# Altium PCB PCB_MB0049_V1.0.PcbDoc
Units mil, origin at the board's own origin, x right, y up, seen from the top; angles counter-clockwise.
Board outline 787.4 x 3937.01 mil, 2 copper layers (Top Layer, Bottom Layer); 21 components, 22 nets, 58 pads, 9 vias.
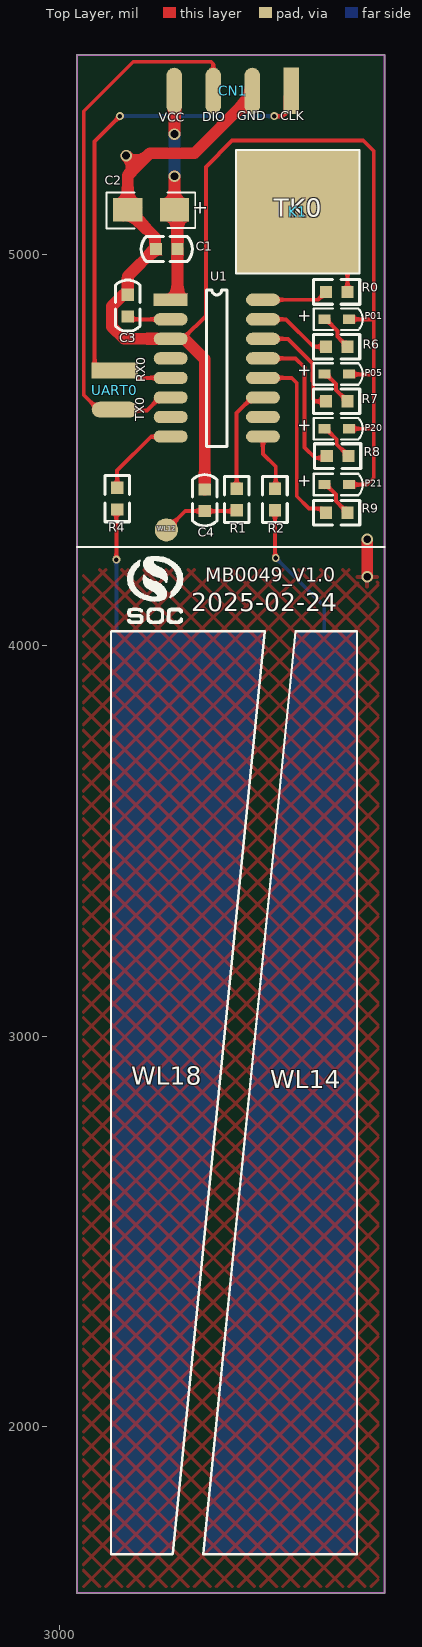
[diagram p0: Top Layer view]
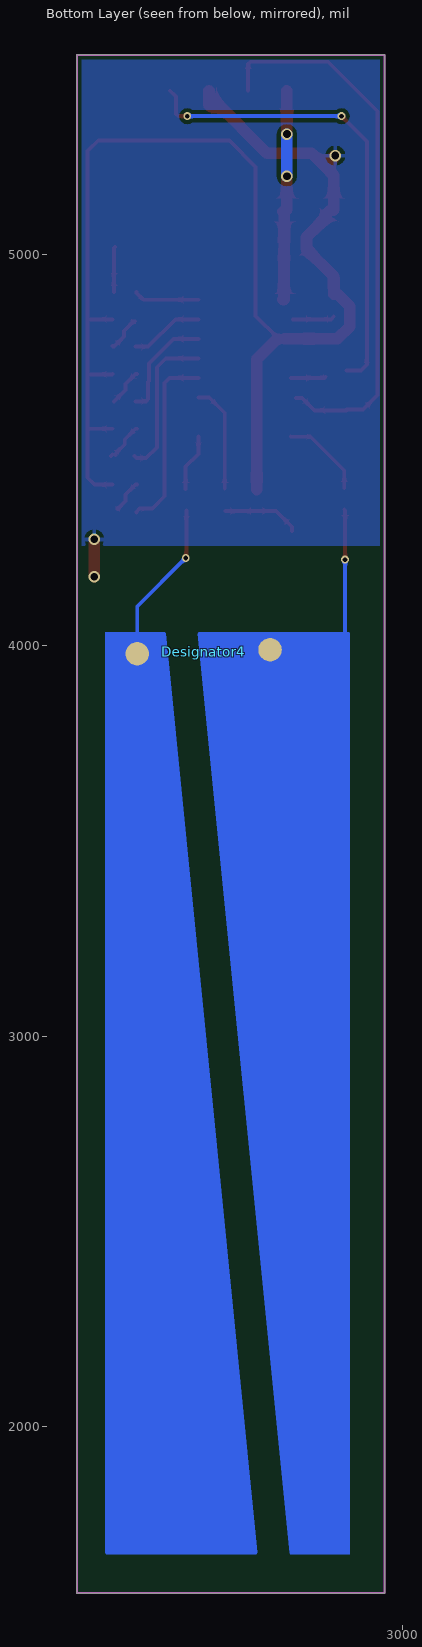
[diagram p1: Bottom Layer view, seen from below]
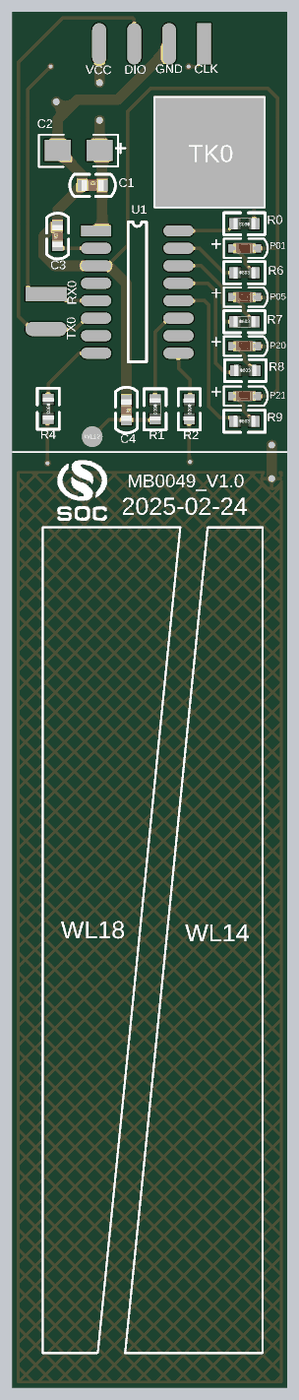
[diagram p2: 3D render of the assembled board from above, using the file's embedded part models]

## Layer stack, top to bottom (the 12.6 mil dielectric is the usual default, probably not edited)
Top Solder: solder mask 0.4, Solder Resist, Dk 3.5
Top Layer: signal copper 1.4
Dielectric 1: dielectric 12.6, FR-4, Dk 4.8
Bottom Layer: signal copper 1.4
Bottom Solder: solder mask 0.4, Solder Resist, Dk 3.5

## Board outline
3045,1574.8 3045,5511.81 3832.4,5511.81 3832.4,1574.8

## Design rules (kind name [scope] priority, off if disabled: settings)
Clearance [All] p1: gap=10 ignorepadtopadclearanceinfootprint=FALSE except(0: Arc-Hole Track-Hole SMDPad-Hole THPad-Hole Via-Hole Fill-Hole Poly-Hole Region-Hole Text-Hole)
PolygonConnect [All] p1: connectstyle=Relief reliefconductorwidth=10 reliefentries=4 polygonreliefangle="90 Angle" airgapwidth=10
RoutingVias [All] p1: holewidth=28 width=50 viastyle="Through Hole" minholewidth=28 minwidth=50 maxholewidth=28 maxwidth=50
SolderMaskExpansion [All] p1: expansion=4 istentingtop=FALSE
Width [All] p1: maxlimit=30 minlimit=10 preferedwidth=10
30 further rules are at their usual default settings.

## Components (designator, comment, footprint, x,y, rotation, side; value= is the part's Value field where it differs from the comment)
C1 "104" C0603-SMT 3275,5015 r0 top
C2 "A/10uF/16V" A-3216 3295,5115 r180 top
C3 "103" C0603-SMT 3175,4870 r90 top
C4 "15pf" C0603-SMT 3372,4372 r270 top
CN1 "CN4" HDR2.54-WS-4P 3444,5361.26 r180 top
Designator4 "Comment" KEY-WL38-1 3438,3264 r0 top
K1 "K-QM" KEY-WL38-2 3610,5110 r0 top
P01 "LED" LED-0603-SMT 3710,4835 r0 top (schematic designator L1)
P05 "LED" LED-0603-SMT 3710,4695 r0 top (schematic designator L2)
P20 "LED" LED-0603-SMT 3710,4555 r0 top (schematic designator L3)
P21 "LED" LED-0603-SMT 3710,4412 r0 top (schematic designator L4)
R0 "510R" R0603-SMT 3710,4905 r180 top
R1 "510R" R0603-SMT 3454,4374 r270 top
R2 "510R" R0603-SMT 3552,4374 r270 top
R4 "510R" R0603-SMT 3148,4376 r270 top
R6 "5.1K" R0603-SMT 3710,4765 r0 top
R7 "5.1K" R0603-SMT 3710,4625 r0 top
R8 "5.1K" R0603-SMT 3712.44,4485 r0 top
R9 "5.1K" R0603-SMT 3710,4340 r0 top
U1 "SC92F8481" SOP16 3285,4885 r0 top
UART0 "CON1*2" HDR2.54-WS-2P 3205.74,4654 r270 top

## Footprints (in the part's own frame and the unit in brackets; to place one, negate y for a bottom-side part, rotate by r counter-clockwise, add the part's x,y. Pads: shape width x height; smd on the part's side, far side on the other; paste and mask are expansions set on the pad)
A-3216 [mil]
  rect 75x60 smd: 1(0,0) 2(120,0)
  silkscreen extent -53,-45 174,47
C0603-SMT [mm]
  rect 0.8x0.8 smd: 1(-0.7,0) 2(0.7,0)
  silkscreen extent -1.66,-0.8 1.66,0.8, body extent -0.8,-0.4 0.8,0.4, height 0.3
HDR2.54-WS-2P [mm] "2P卧式贴片排针2.54"
  rect 1.02x3 smd: 1(-1.27,-1.619)
  oval 1.02x3 smd: 2(1.27,-1.619)
HDR2.54-WS-4P [mm] "4P卧式贴片排针2.54"
  rect 1.02x3 smd: 1(-3.81,-1.492)
  oval 1.02x3 smd: 2(-1.27,-1.492) 3(1.27,-1.492) 4(3.81,-1.492)
KEY-WL38-1 [mil]
  round 60 smd far side: 1(-100,725) 2(240,715)
  Bottom Layer region: 319.77,-1589.7 -64.5,-1589.7 -67.86,-1586 167.45,767.09 319.77,767.09
  Bottom Layer region: 83.34,763.59 -151.97,-1589.5 -304.29,-1589.5 -304.29,767.29 79.98,767.29
  Bottom Layer region: 320.77,-1587.7 -63.5,-1587.7 -66.86,-1584 168.45,769.09 320.77,769.09
  Bottom Layer region: 84.34,765.59 -150.97,-1587.5 -303.29,-1587.5 -303.29,769.29 80.98,769.29
  Bottom Layer region: 321.77,-1586.7 -62.5,-1586.7 -65.86,-1583 169.45,770.09 321.77,770.09
  Bottom Layer region: 85.34,766.59 -149.97,-1586.5 -302.29,-1586.5 -302.29,770.29 81.98,770.29
  silkscreen extent -306,-1590 324,773
KEY-WL38-2 [mm]
  rect 8x8 smd mask+0.102: 1(0,0)
LED-0603-SMT [mm]
  rect 0.8x0.6 smd: A(-0.8,0) K(0.8,0)
  silkscreen extent -1.5,-0.7 1.69,0.7, body extent -0.81,-0.4 0.81,0.4, height 0.6
R0603-SMT [mm]
  rect 0.8x0.8 smd: 1(-0.7,0) 2(0.7,0)
  silkscreen extent -1.5,-0.8 1.5,0.8, body extent -0.8,-0.41 0.8,0.41, height 0.45
SOP16 [mm]
  rect 2.2x0.8 smd: 1(0,0)
  oval 2.2x0.8 smd: 2(0,-1.27) 3(0,-2.54) 4(0,-3.81) 5(0,-5.08) 6(0,-6.35) 7(0,-7.62) 8(0,-8.89) 9(6,-8.89) 10(6,-7.62) 11(6,-6.35) 12(6,-5.08) 13(6,-3.81) 14(6,-2.54) 15(6,-1.27) 16(6,0)
  silkscreen extent 2.33,-9.53 3.67,0.64

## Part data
C1 C4: library part C_3, "C"
C2: library part T-A/10uF/16V
C3: library part C_1, "C"
CN1: "4P-SOCKET"
R0 R1 R2 R4 R6 R7 R8 R9: library part R, "RES"
U1: "电压:2.4V-5.5V;ROM:128KB;RAM:256B+8KB;32/16/8/4MHz"

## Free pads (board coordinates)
  round 59.06 smd mask+4: 2(3274,4296)

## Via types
v1: diameter 30, hole 20, Top Layer to Bottom Layer, tented both sides, 5 vias
v2: diameter 20, hole 12, Top Layer to Bottom Layer, tented both sides, 4 vias

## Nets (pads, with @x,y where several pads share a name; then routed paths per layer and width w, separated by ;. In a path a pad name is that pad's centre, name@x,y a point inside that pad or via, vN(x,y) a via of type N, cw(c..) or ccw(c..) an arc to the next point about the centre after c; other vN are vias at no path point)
CLK: CN1.1 U1.5 UART0.1 | length 1302.9
  Top Layer w10: UART0.1 3105.44,4704 3090.37,4719.08 3090.37,4732.71 3090,4733.08 3090,5290 v2(3155,5355) ; UART0.1@3196,4688 3199,4685 U1.5 ; v2(3550,5355) 3573.06,5355 3578.92,5360.86 3578.92,5404.92 CN1.1
  Bottom Layer w10: v2(3155,5355) v2(3550,5355)
DIO: CN1.3 U1.6 UART0.2 | length 1419.2
  Top Layer w10: UART0.2@3142,4602 3224.44,4602 3256.44,4634 U1.6@3272,4634 ; UART0.2 3100,4604 3062.5,4641.5 3062.5,5367.5 3189.31,5494.31 3388.14,5494.31 3394,5488.45 CN1.3
GND: C1.1 C2.2 C3.2 C4.1 CN1.2 P01.K P05.K P20.K P21.K U1.3 | length 3661.8
  Top Layer w10: U1.3@3302,4788 3319,4788 3375,4844 3375,5225.32 3442.16,5292.48 3777.84,5292.48 3804.9,5265.41 3804.9,4429.57 3787.33,4412 P21.K ; P20.K 3799,4555 3804,4550 ; P05.K 3741.5,4694.75 3742.24,4694 3800,4694 ; P01.K 3801,4835 3802,4836
  Top Layer w30: v1(3171,5254) 3198.5,5226.5 ; C1.1@3245,5015 3175,4945 3175,4899 3164.71,4899 3134.25,4868.54 3134.25,4816.34 3165.59,4785 U1.3 U1.3@3302,4785 ; C1.1@3245,5020 3245,5045 3197.5,5092.5 3197.5,5100 3182.5,5115 C2.2 3175,5203 3198.5,5226.5 ; U1.3@3316,4784 3321.19,4784 3372,4733.19 C4.1 ; CN1.2@3486,5394 3480,5394 3346,5260 3232,5260 3198.5,5226.5 ; CN1.2@3489.31,5379.08 3494,5383.77 CN1.2 ; v1(3788,4176) v1@3788,4270
  other v1: 3788,4272
NetC3_1: C3.1 U1.2 | length 108.1
  Top Layer w10: C3.1 3182.44,4835 U1.2@3280,4835
NetC4_2: C4.2 pad.2 R1.2 | length 198.5
  Top Layer w10: pad.2@3282,4292.48 3282,4304 3322.44,4344.44 C4.2 3372.44,4344 R1.2@3452,4344
NetK0_9: 
NetK1_1: K1.1 R0.1 | length 116.1
  Top Layer w10: K1.1@3735,5020 3737.56,5017.44 R0.1
NetK2_1: Designator4.2 R2.2 | length 419.6
  Top Layer w10: R2.2 3552,4232.71 3552.09,4232.62 3552.09,4225.91 v2(3554,4224)
  Bottom Layer w10: v2(3554,4224) 3678,4100 Designator4.2
NetK4_1: Designator4.1 R4.2 | length 547
  Top Layer w10: v2(3146,4220) 3146,4346.44 R4.2
  Bottom Layer w10: v2(3146,4220) 3146,3998 3155,3989 Designator4.1
NetL1_A: P01.A R6.2 | length 91.3
  Top Layer w10: P01.A@3684,4830 3687.44,4830 3712,4805.44 3712,4790.56 R6.2 ; R6.2@3740,4765 R6.2@3741.5,4766.5
NetL2_A: P05.A R7.2 | length 96.8
  Top Layer w10: P05.A 3682.44,4695 3708,4669.44 3708,4654.56 R7.2
NetL3_A: P20.A R8.2 | length 97.2
  Top Layer w10: P20.A 3682.44,4555 3710,4527.44 3710,4515 3734,4491 R8.2@3734,4488 ; R8.2@3741.5,4488.5 R8.2@3745,4485
NetL4_A: P21.A R9.2 | length 85.1
  Top Layer w10: P21.A 3682.44,4412 3708,4386.44 3708,4369.56 3727.56,4350 R9.2@3728,4350
NetR0_2: R0.2 U1.16 | length 168.5
  Top Layer w10: U1.16 3662.44,4885 3680,4902.56 R0.2@3680,4905
NetR1_1: R1.1 U1.11 | length 277.4
  Top Layer w10: R1.1 3454,4595.34 3493.66,4635 U1.11
NetR2_1: R2.1 U1.9 | length 148.6
  Top Layer w10: U1.9 3521.22,4490.78 3554,4458 R2.1@3554,4400.02
NetR4_1: R4.1 U1.8 | length 217.5
  Top Layer w10: R4.1 3148,4448 3234.48,4534.48 3284.48,4534.48 U1.8
NetR6_1: R6.1 U1.15 | length 190.2
  Top Layer w10: U1.15 3580,4835 3650,4765 R6.1
NetR7_1: R7.1 U1.14 | length 279.7
  Top Layer w10: U1.14 3585,4785 3647.76,4722.24 3647.76,4676.98 3650,4674.73 3650,4630.86 3655.86,4625 R7.1
NetR8_1: R8.1 U1.13 | length 391.6
  Top Layer w10: U1.13 3605,4735 3627.76,4712.24 3627.76,4507.24 3655,4480 3680,4480 R8.1@3685,4485
NetR9_1: R9.1 U1.12 | length 473
  Top Layer w10: U1.12 3595,4685 3607.76,4672.24 3607.76,4382.24 3639.25,4350.75 3671.69,4350.75 3680,4342.44 R9.1@3680,4340
VCC: C1.2 C2.1 CN1.4 U1.1 | length 533.6
  Top Layer w30: C2.1 v1(3295,5201) ; v1(3295,5309) CN1.4@3295,5420 ; U1.1@3305,4885 3303.31,4885 3302.56,4885.75 C1.2 3301.81,5015.75 3301.81,5106.81 C2.1@3305,5110
  Bottom Layer w30: v1(3295,5201) v1(3295,5309)
pads on no net: U1.4 U1.7 U1.10

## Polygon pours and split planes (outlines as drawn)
GND on Top Layer "GND_L01_P000" (hatched 45Degree grid 40 track 8, pour order 0): 3817,4194 3817,1593 3820,1590 3812,1582 3055,1582 3055,4194
GND on Bottom Layer "GND_L02_P005" (solid, remove dead copper, pour order 5): 3046,5510 3047,5509 3047,4255 3831,4255 3832,4256 3830,4258 3830,5510 3045,5510

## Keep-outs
Keep-Out Layer:
  the board outline again, w5

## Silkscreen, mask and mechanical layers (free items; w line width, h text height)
Top Overlay:
  drawing of 10 lines, arcs and shapes, not listed
  text "GND" at 3455,5336.43 h40
  text "CLK" at 3566,5336.43 h40
  text "DIO" at 3366,5334.43 h40
  text "VCC" at 3255,5333.43 h40
  text "TK0" at 3549,5081.85 h80
  text "RX0" at 3227.57,4674 h40 r90
  text "TX0" at 3225.57,4574 h40 r90
  text "WL12" at 3251,4290 h20
  text "MB0049_V1.0" at 3374.1,4151.52 h60
  text "2025-02-24" at 3338.1,4072.83 h80
  text "WL18" at 3184,2860.85 h80
  text "WL14" at 3540,2852 h80
Mechanical 1:
  the board outline again, w5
